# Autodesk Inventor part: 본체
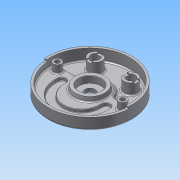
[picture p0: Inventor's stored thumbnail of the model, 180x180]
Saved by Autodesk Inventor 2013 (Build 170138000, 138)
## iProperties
Created: 2015-04
Part Number: 본체
Material: 알루미늄 6061
Document SubType Name: Modeling
Designer: Administrator
Density: 2.71 g/cm^3
Mass: 1039.65 g
Surface Area: 1017.49 cm^2
Volume: 383.635 cm^3
Author: Administrator
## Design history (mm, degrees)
sketch "스케치1"
  geometry: C1 r 95 at (0, 0); 1 further point
  constraints: 1 centre point, 1 coincident
  dimensions: "d0" = 190 diameter of C1
extrude "돌출1" new body sketch "스케치1" distance "d2" = 32; taper "d3" = 0 deg
sketch "스케치2"
  geometry: C1 r 95 at (0, 0) reference; C2 r 90 at (0, 0)
  constraints: 1 centre point, 1 coincident
  dimensions: "d5" = 180 diameter of C2
extrude "돌출2" cut sketch "스케치2" distance "d6" = 25; taper "d7" = 0 deg
sketch "스케치3"
  geometry: L1 (95, 0)-(-95, 0); L2 (0, 0)-(94.638, -8.28); L3 (0, 0)-(-94.638, -8.28); C1 r 90 at (0, 0) reference; A1 r 95 centre (0, 0) between (95, 0) and (-95, 0) reference
  constraints: 6 end point, 4 point on circle, 1 coincident, 1 horizontal, 1 midpoint
  dimensions: "d9" = 5 deg angle of L2 L1; "d10" = 5 deg angle of L3 L1
extrude "돌출3" cut sketch "스케치3" distance "d11" = 5; taper "d12" = 0 deg
sketch "스케치4"
  geometry: L1 (76.916, 12)-(47.117, 12); L2 (-76.916, 12)-(-47.117, 12); A1 r 90 centre (0, 0) between (-89.658, -7.844) and (89.658, -7.844) reference; A2 r 42 centre (0, 0) between (38.056, 17.769) and (-38.056, 17.769); A3 r 90 centre (0, 0) between (89.658, -7.844) and (-89.658, -7.844) reference; A4 r 10 centre (76.916, 22) between (76.916, 12) and (86.53, 24.75); A5 r 10 centre (-76.916, 22) between (-86.53, 24.75) and (-76.916, 12); A6 r 10 centre (-47.117, 22) between (-47.117, 12) and (-38.056, 17.769); A7 r 10 centre (47.117, 22) between (38.056, 17.769) and (47.117, 12); 1 further point
  constraints: 13 point on circle, 8 tangent, 5 centre point, 4 end point, 2 collinear, 1 coincident, 1 horizontal
  dimensions: "d13" = 84 diameter of A2; "d14" = 12 distance from line of A1.centre L2; "d93" = 10 radius of A4; "d94" = 10 radius of A5; "d95" = 10 radius of A6; "d96" = 10 radius of A7
extrude "돌출4" join sketch "스케치4" distance "d15" = 7; taper "d16" = 0 deg
sketch "스케치5"
  geometry: L1 (-47.117, 12)-(-76.916, 12) reference; L2 (-41, -19)-(-41, -14); L3 (-59, -14)-(-59, -19); L4 (59, -19)-(59, -14); L5 (41, -14)-(41, -19); A1 r 42 centre (0, 0) between (38.056, 17.769) and (-38.056, 17.769) reference; A2 r 41 centre (0, -19) between (-41, -19) and (41, -19); A3 r 59 centre (0, -19) between (-59, -19) and (59, -19); A4 r 9 centre (-50, -14) between (-41, -14) and (-59, -14); A5 r 9 centre (50, -14) between (59, -14) and (41, -14); 3 further points
  constraints: 8 end point, 8 point on circle, 8 tangent, 4 centre point, 4 parallel, 1 coincident, 1 perpendicular, 1 vertical alignment
  dimensions: "d24" = 41 radius of A2; "d25" = 19 distance of A2.centre A1.centre; "d27" = 59 radius of A3; "d28" = 5 distance of L4.start L4.end
extrude "돌출5" cut sketch "스케치5" distance "d29" = 7; taper "d30" = 0 deg
sketch "스케치6"
  geometry: C1 r 35 at (0, 0); A1 r 90 centre (0, 0) between (-86.53, 24.75) and (86.53, 24.75) reference; 2 further points
  constraints: 1 centre point, 1 coincident
  dimensions: "d31" = 70 diameter of C1
extrude "돌출6" join sketch "스케치6" distance "d32" = 10; taper "d33" = -10 deg
hole "구멍1" diameter "d36" = 23; stored, may be unused: countersink angle "d40" = 90 deg, drill point angle "d42" = 118 deg; dims "d34" = 10, "d35" = 10, "d37" = 6, "d38" = 50, "d39" = 15, "d41" = 8
sketch "스케치7"
  geometry: C1 r 35 at (0, 0) reference; C2 r 9 at (74, 0); A1 r 59 centre (0, -19) between (-59, -19) and (59, -19) reference
  constraints: 1 centre point, 1 horizontal alignment
  dimensions: "d44" = 18 diameter of C2; "d45" = 74 horizontal distance of A1.centre C2.centre
extrude "돌출7" join sketch "스케치7" distance "d46" = 18; taper "d47" = 0 deg
sketch "스케치8"
  geometry: C1 r 9 at (-74, 0) reference
hole "구멍2" sketch "스케치8" at (-74, 0) diameter "d48" = 11; stored, may be unused: countersink angle "d52" = 90 deg, drill point angle "d54" = 118 deg; dims "d49" = 6, "d50" = 18, "d51" = 11, "d53" = 8
sketch "스케치9"
  geometry: C1 r 15 at (40, 52); A1 r 90 centre (0, 0) between (86.53, 24.75) and (-86.53, 24.75) reference; 2 further points
  constraints: 1 centre point
  dimensions: "d55" = 52 vertical distance of A1.centre C1.centre; "d56" = 40 horizontal distance of C1.centre A1.centre; "d57" = 30 diameter of C1
extrude "돌출8" join sketch "스케치9" distance "d58" = 25; taper "d59" = 0 deg
hole "구멍3" diameter "d62" = 20; stored, may be unused: countersink angle "d66" = 90 deg, drill point angle "d68" = 118 deg; dims "d60" = 10, "d61" = 10, "d63" = 6, "d64" = 18, "d65" = 11, "d67" = 8
sketch "스케치10"
  geometry: L1 (13.748, 6)-(-13.748, 6); L2 (-13.748, -6)-(13.748, -6); L3 (-74, 13.748)-(-74, -13.748); L4 (-86, -13.748)-(-86, 13.748); A1 r 15 centre (0, 0) between (-13.748, 6) and (-13.748, -6) reference; A2 r 15 centre (-80, 0) between (-74, 13.748) and (-74, -13.748) reference; 1 further point
  constraints: 8 end point, 8 point on circle, 3 parallel, 2 horizontal, 1 vertical
  dimensions: "d69" = 12 distance between parallel lines of L2 L1; "d70" = 12 distance between parallel lines of L3 L4
extrude "돌출9" cut sketch "스케치10" distance "d71" = 3; taper "d72" = 0 deg
sketch "스케치11"
  geometry: L1 (0, 0)-(50.912, -50.912); L2 (0, 0)-(-50.912, -50.912); L3 (0, 0)-(0, -72); C1 r 95 at (0, 0) reference; A1 r 51 centre (0, 0) between (-36.062, -36.062) and (36.062, -36.062); A2 r 72 centre (0, 0) between (-50.912, -50.912) and (50.912, -50.912)
  constraints: 6 end point, 5 point on circle, 2 centre point, 2 coincident, 2 point on line, 1 vertical
  dimensions: "d74" = 51 radius of A1; "d75" = 90 deg angle of L1 L2; "d76" = 45 deg angle of L3 L1; "d77" = 72 radius of A2
extrude "돌출10" join sketch "스케치11" distance "d78" = 5; taper "d79" = 0 deg
fillet "모깎기3" dims "d97" = 3, "d98" = 5, "d99" = 0.3, "d100" = 1
fillet "모깎기4" dims "d101" = 3, "d102" = 5
chamfer "모따기2" distance "d103" = 1; stored, may be unused: second distance "d104" = 2, angle "d105" = 45 deg
sketch "스케치13"
  geometry: C1 r 68 at (0, 0); 1 further point
  constraints: 1 centre point, 1 coincident, 1 other
  dimensions: "d106" = 136 diameter of C1
feature "엠보싱2" sketch "스케치13" dims "d107" = 0.5, "d108" = 0
fillet "모깎기7" dims "d111" = 5
fillet "모깎기8" dims "d112" = 3
node "솔리드1"
mirror "대칭1"
other parameters: "d22" = 59, "d73" = 72
